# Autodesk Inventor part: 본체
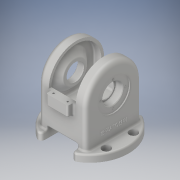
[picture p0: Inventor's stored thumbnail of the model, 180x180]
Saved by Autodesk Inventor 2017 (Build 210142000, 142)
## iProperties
Part Number: 본체
Material: 알루미늄 6061
Document SubType Name: Modeling
Designer: MRC
Density: 2.7 g/cm^3
Appearance: 알루미늄 - 평지
Mass: 1199.23 g
Surface Area: 1052.12 cm^2
Volume: 444.159 cm^3
Author: MRC
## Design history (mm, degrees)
sketch "스케치3"
  geometry: C1 r 71 at (0, 0); 1 further point
  constraints: 1 centre point, 1 coincident
  dimensions: "d4" = 142 diameter of C1
extrude "돌출2" new body sketch "스케치3" distance "d5" = 13; taper "d6" = 0 deg
sketch "스케치4"
  geometry: L1 (-44, -51)-(44, -51); L2 (44, -51)-(44, 51); L3 (44, 51)-(-44, 51); L4 (-44, 51)-(-44, -51); L5 (-44, -51)-(44, 51); L6 (44, -51)-(-44, 51); 1 further point
  constraints: 12 end point, 2 midpoint, 2 parallel, 1 horizontal, 1 perpendicular
  dimensions: "d7" = 88 distance of L3.end L2.end; "d8" = 102 distance of L2.end L1.end
extrude "돌출3" join sketch "스케치4" distance "d9" = 119; taper "d10" = 0 deg
fillet "모깎기1" dims "d11" = 51
node "작업 평면1"
sketch "스케치6"
  geometry: L1 (28, -19)-(-28, -19); L2 (-28, -19)-(-28, 19); L3 (-28, 19)-(28, 19); L4 (28, 19)-(28, -19); L5 (28, -19)-(-28, 19); L6 (-28, -19)-(28, 19); 1 further point
  constraints: 12 end point, 2 midpoint, 2 parallel, 1 horizontal, 1 perpendicular
  dimensions: "d13" = 56 distance of L2.end L3.end; "d14" = 38 distance of L1.end L2.end
extrude "돌출4" cut sketch "스케치6" stored distance "d15" = 81; taper "d16" = 0 deg
node "작업 평면3"
sketch "스케치9"
  geometry: L1 (20, -61)-(-20, -61); L2 (-20, -61)-(-20, 61); L3 (-20, 61)-(20, 61); L4 (20, 61)-(20, -61); L5 (20, -61)-(-20, 61); L6 (-20, -61)-(20, 61); 1 further point
  constraints: 12 end point, 2 midpoint, 2 parallel, 1 horizontal, 1 perpendicular
  dimensions: "d18" = 122 distance of L3.end L1.start; "d19" = 40 distance of L2.end L3.end
extrude "돌출5" join sketch "스케치9" distance "d20" = 20; taper "d21" = 0 deg
sketch "스케치11"
  geometry: L1 (13, 51)-(81, 51) reference; L2 (13, -51)-(81, -51) reference; L3 (40, 46)-(81, 46); L4 (81, -46)-(40, -46); L5 (40, 46)-(40, -46); L6 (0, -65.246)-(0, 65.246) reference; A1 r 51 centre (81, 0) between (81, -51) and (81, 51) reference; A2 r 46 centre (81, 0) between (81, -46) and (81, 46); 1 further point
  constraints: 6 end point, 2 point on circle, 1 centre point
  dimensions: "d22" = 5 radial gap between concentric circles of A1 A2; "d23" = 40 distance between parallel lines of L5 L6; "d24" = 5 distance between parallel lines of L2 L4; "d25" = 5 distance between parallel lines of L1 L3
extrude "돌출6" cut sketch "스케치11" stored distance "d26" = 78; taper "d27" = 0 deg
sketch "스케치12"
  geometry: L1 (-25, 183)-(25, 183); L2 (25, 183)-(25, 81); L3 (25, 81)-(-25, 81); L4 (-25, 81)-(-25, 183); L5 (-44, 132)-(44, 132) reference; L6 (-25, 183)-(25, 81); L7 (25, 183)-(-25, 81); 2 further points
  constraints: 12 end point, 3 midpoint, 2 parallel, 1 horizontal, 1 perpendicular
  dimensions: "d28" = 50 distance of L1.start L1.end; "d29" = 102 distance of L1.end L2.end
extrude "돌출7" cut sketch "스케치12" stored distance "d30" = 150; taper "d31" = 0 deg
sketch "스케치13"
  geometry: L1 (25, 81)-(-25, 81) reference; L2 (39, 81)-(25, 81) reference; L3 (-25, 81)-(-39, 81) reference; L4 (-39, 127)-(-39, 81) reference; L5 (-39, 114.5)-(-27, 102.5); L6 (-27, 102.5)-(-27, 81); L7 (-39, 81)-(-39, 114.5); L8 (-39, 127)-(-25, 127) reference; L9 (-39, 81)-(-27, 81); 1 further point
  constraints: 8 end point, 2 point on line, 1 collinear, 1 parallel, 1 vertical
  dimensions: "d32" = 12 horizontal distance of L5.start L5.end; "d33" = 45 deg angle of L5 L8; "d34" = 67 diameter of L5.start L3
revolve "회전1" sketch "스케치13" stored, may be unused: angle "d35" = 90 deg
sketch "스케치15"
  geometry: C1 r 30 at (51, 68); A1 r 51 centre (51, 68) between (102, 68) and (0, 68) reference; 1 further point
  constraints: 1 centre point, 1 coincident
  dimensions: "d36" = 60 diameter of C1
extrude "돌출8" cut sketch "스케치15" distance "d37" = 2; taper "d38" = 0 deg
sketch "스케치16"
  geometry: C1 r 30 at (0, 0) reference; C2 r 18.5 at (0, 0); 1 further point
  constraints: 1 centre point, 1 coincident
  dimensions: "d39" = 37 diameter of C2
extrude "돌출9" cut sketch "스케치16" distance "d40" = 13; taper "d41" = 0 deg
sketch "스케치17"
  geometry: C1 r 18.5 at (0, 0) reference; C2 r 16 at (0, 0); 1 further point
  constraints: 1 centre point, 1 coincident
  dimensions: "d42" = 32 diameter of C2
extrude "돌출10" cut sketch "스케치17" distance "d43" = 13; taper "d44" = 0 deg
sketch "스케치18"
  geometry: C1 r 16 at (0, 0) reference; A1 r 23 centre (0, 0) between (0, 23) and (23, 0); 3 further points
  constraints: 4 point on circle, 2 horizontal alignment, 2 vertical alignment, 1 centre point, 1 coincident
  dimensions: "d45" = 46 diameter of A1
hole "구멍1" sketch "스케치18" at (0, 23), (23, 0), (0, -23), (-23, 0) diameter "d46" = 3.242; stored, may be unused: countersink angle "d50" = 90 deg, drill point angle "d52" = 118 deg; dims "d47" = 8, "d48" = 4, "d49" = 2, "d51" = 10
sketch "스케치20"
  geometry: C1 r 30 at (0, 0); 1 further point
  constraints: 1 centre point, 1 coincident
  dimensions: "d56" = 60 diameter of C1
extrude "돌출12" cut sketch "스케치20" distance "d57" = 22; taper "d58" = 0 deg
sketch "스케치21"
  geometry: C1 r 14 at (0, 0); 1 further point
  constraints: 1 centre point, 1 coincident
  dimensions: "d59" = 28 diameter of C1
extrude "돌출13" cut sketch "스케치21" distance "d60" = 15; taper "d61" = 0 deg
sketch "스케치22"
  geometry: C1 r 11 at (0, 0); 1 further point
  constraints: 1 centre point, 1 coincident
  dimensions: "d62" = 22 diameter of C1
extrude "돌출14" cut sketch "스케치22" stored distance "d63" = 15; taper "d64" = 0 deg
sketch "스케치23"
  geometry: A1 r 23 centre (0, 0) between (0, -23) and (-23, 0); 3 further points
  constraints: 4 point on circle, 2 horizontal alignment, 2 vertical alignment, 1 centre point, 1 coincident
  dimensions: "d65" = 46 diameter of A1
hole "구멍2" sketch "스케치23" at (0, -23), (-23, 0), (0, 23), (23, 0) diameter "d66" = 3.242; stored, may be unused: countersink angle "d70" = 90 deg, drill point angle "d72" = 118 deg; dims "d67" = 8, "d68" = 4, "d69" = 2, "d71" = 10
sketch "스케치24"
  geometry: L1 (-55, -25)-(55, -25); L2 (55, -25)-(55, 25); L3 (55, 25)-(-55, 25); L4 (-55, 25)-(-55, -25); L5 (-55, -25)-(55, 25); L6 (55, -25)-(-55, 25); A1 r 30 centre (0, 0) between (28, -10.77) and (28, 10.77) reference; A2 r 30 centre (0, 0) between (-28, 10.77) and (-28, -10.77) reference; 5 further points
  constraints: 12 end point, 4 coincident, 2 midpoint, 2 parallel, 1 horizontal, 1 perpendicular
  dimensions: "d73" = 110 distance of L3.end L2.end; "d74" = 50 distance of L2.end L1.end
hole "구멍3" sketch "스케치24" at (55, 25), (55, -25), (-55, 25), (-55, -25) diameter "d75" = 9; stored, may be unused: countersink angle "d79" = 90 deg, drill point angle "d81" = 118 deg; dims "d76" = 8, "d77" = 15, "d78" = 8.8, "d80" = 22
sketch "스케치25"
  geometry: L1 (-13, 54)-(13, 54); L2 (13, 54)-(13, -54); L3 (13, -54)-(-13, -54); L4 (-13, -54)-(-13, 54); L5 (-13, 54)-(13, -54); L6 (13, 54)-(-13, -54); 5 further points
  constraints: 12 end point, 4 coincident, 2 midpoint, 2 parallel, 1 horizontal, 1 perpendicular
  dimensions: "d82" = 26 distance of L2.end L3.end; "d83" = 108 distance of L1.end L2.end
hole "구멍4" sketch "스케치25" at (13, 54), (-13, 54), (-13, -54), (13, -54) diameter "d84" = 3.242; stored, may be unused: countersink angle "d88" = 90 deg, drill point angle "d90" = 118 deg; dims "d85" = 8, "d86" = 15, "d87" = 8.8, "d89" = 10
sketch "스케치26"
  geometry: L1 (-14.246, -13)-(116.246, -13) reference; 3 further points
  constraints: 1 midpoint, 1 vertical alignment, 1 other
  dimensions: "d91" = 30 distance from line of point (51, 17) L1
feature "엠보싱1" sketch "스케치26" dims "d13" = 56, "d14" = 38, "d92" = 0.5, "d93" = 0
fillet "모깎기2" dims "d94" = 8
fillet "모깎기3" dims "d95" = 6
chamfer "모따기1" distance "d96" = 1; stored, may be unused: second distance "d97" = 2, angle "d98" = 45 deg
fillet "모깎기4" dims "d99" = 3
fillet "모깎기5" dims "d100" = 3
node "솔리드2"
mirror "미러1"
other parameters: "d12" = 71, "d17" = 81
